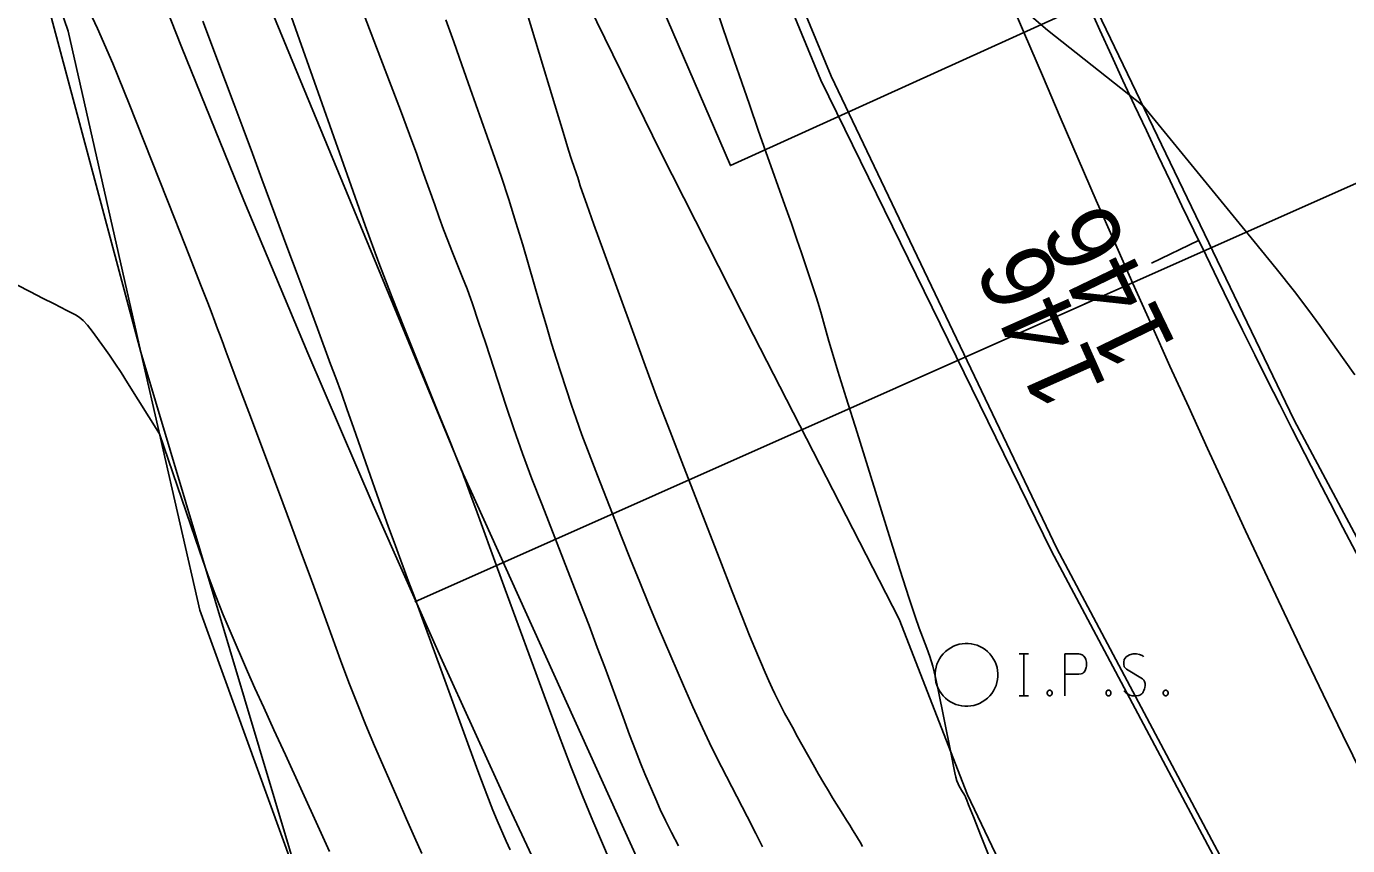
# Model space of a CAD drawing. Extents: x 2030588 to 2035216, y 462285 to 465007.
# Drawn here: x 2031264.3 to 2031314.8, y 464067.3 to 464098.6 of the extents above; entities that cross this region are included whole.
import ezdxf

# ---------------------------------------------------------------- set-up
doc = ezdxf.new("R2010")
doc.units = 0
for name, color, linetype in [('DT_X_Contour_Major', 7, 'Continuous'), ('DT_X_Contour_Minor', 7, 'Continuous'), ('DV_X_Property_Line', 7, 'Continuous'), ('GE_X_Alignment', 7, 'Continuous'), ('GE_X_Alignment_100_Stations', 7, 'Continuous'), ('MD_P_CONST_LIMITS', 7, 'Continuous'), ('PV_X_COP', 7, 'Continuous'), ('PV_X_EOP', 7, 'Continuous'), ('PV_X_Shoulder_Aggregate', 7, 'Continuous'), ('RW_X_CL', 7, 'Continuous'), ('RW_X_CL_100_Stations', 7, 'Continuous'), ('RW_X_Esmt_SH', 7, 'Continuous'), ('SV_P_Mon_Cells_Set', 7, 'Continuous'), ('SV_X_Break_Lines', 7, 'Continuous'), ('SV_X_Toe_of_Slope', 7, 'Continuous'), ('VG_X_Tree_Line_Lt', 7, 'Continuous')]:
    doc.layers.add(name, color=color, linetype=linetype)

msp = doc.modelspace()

# ---------------------------------------------------------------- linework, layer by layer
at = {"layer": 'DT_X_Contour_Major'}
for points in [[(2031282.783, 464101.292), (2031284.067, 464097.017), (2031284.494, 464095.597), (2031284.813, 464094.543), (2031285.024, 464093.856), (2031285.127, 464093.534), (2031285.256, 464093.166), (2031285.302, 464093.035), (2031285.341, 464092.917), (2031285.375, 464092.813), (2031285.402, 464092.722), (2031285.468, 464092.498), (2031285.542, 464092.277), (2031285.718, 464091.781), (2031285.995, 464091.012), (2031286.373, 464089.968), (2031287.514, 464086.819), (2031287.954, 464085.618), (2031288.417, 464084.377), (2031288.903, 464083.096), (2031289.412, 464081.775), (2031290.801, 464078.2), (2031291.275, 464076.983), (2031291.657, 464076.014), (2031291.946, 464075.292), (2031292.143, 464074.817), (2031292.544, 464073.883), (2031292.685, 464073.558), (2031292.806, 464073.284), (2031292.909, 464073.062), (2031292.993, 464072.891), (2031293.191, 464072.504), (2031293.283, 464072.328), (2031293.413, 464072.088), (2031293.579, 464071.786), (2031293.782, 464071.421), (2031294.372, 464070.363), (2031294.585, 464069.987), (2031294.779, 464069.649), (2031294.956, 464069.352), (2031295.114, 464069.094), (2031295.514, 464068.46), (2031295.654, 464068.235), (2031295.777, 464068.039), (2031295.882, 464067.87), (2031295.969, 464067.728), (2031296.176, 464067.387), (2031296.262, 464067.229)], [(2031279.413, 464066.965), (2031279.135, 464067.589), (2031278.833, 464068.273), (2031278.508, 464069.016), (2031277.612, 464071.078), (2031277.278, 464071.862), (2031276.951, 464072.669), (2031276.628, 464073.499), (2031276.311, 464074.35), (2031275.473, 464076.652), (2031275.143, 464077.553), (2031274.782, 464078.532), (2031274.391, 464079.586), (2031273.968, 464080.718), (2031272.798, 464083.837), (2031272.409, 464084.876), (2031272.117, 464085.655), (2031271.923, 464086.172), (2031271.827, 464086.429), (2031271.701, 464086.766), (2031271.653, 464086.895), (2031271.604, 464087.027), (2031271.553, 464087.163), (2031271.501, 464087.304), (2031271.36, 464087.684), (2031271.233, 464088.014), (2031270.956, 464088.72), (2031270.531, 464089.8), (2031269.956, 464091.255), (2031268.225, 464095.636), (2031267.599, 464097.178), (2031267.018, 464098.517), (2031266.484, 464099.653)]]:
    msp.add_lwpolyline(points, dxfattribs=at)
at = {"layer": 'DT_X_Contour_Minor'}
for points in [[(2031289.871, 464101.627), (2031291.105, 464098.019), (2031291.544, 464096.739), (2031291.935, 464095.608), (2031292.277, 464094.625), (2031292.571, 464093.789), (2031293.292, 464091.759), (2031293.543, 464091.048), (2031293.757, 464090.437), (2031293.932, 464089.927), (2031294.07, 464089.517), (2031294.386, 464088.558), (2031294.5, 464088.209), (2031294.602, 464087.881), (2031294.694, 464087.574), (2031294.775, 464087.289), (2031294.978, 464086.557), (2031295.101, 464086.132), (2031295.322, 464085.407), (2031295.638, 464084.381), (2031296.051, 464083.055), (2031297.28, 464079.117), (2031297.697, 464077.788), (2031298.027, 464076.756), (2031298.27, 464076.02), (2031298.426, 464075.581), (2031298.726, 464074.806), (2031298.836, 464074.488), (2031298.945, 464074.119), (2031299.05, 464073.696), (2031299.152, 464073.222), (2031299.624, 464070.883), (2031299.792, 464070.049), (2031299.829, 464069.882), (2031299.87, 464069.74), (2031299.914, 464069.624), (2031299.961, 464069.532), (2031300.09, 464069.319), (2031300.134, 464069.245), (2031300.169, 464069.182), (2031300.196, 464069.13), (2031300.213, 464069.089), (2031300.249, 464068.994), (2031300.318, 464068.816), (2031300.5, 464068.356), (2031300.795, 464067.612), (2031301.202, 464066.584)], [(2031276.986, 464099.628), (2031278.181, 464096.479), (2031278.596, 464095.383), (2031278.942, 464094.457), (2031279.221, 464093.699), (2031279.432, 464093.112), (2031279.906, 464091.77), (2031280.08, 464091.283), (2031280.248, 464090.826), (2031280.41, 464090.401), (2031280.566, 464090.006), (2031280.973, 464088.994), (2031281.143, 464088.551), (2031281.347, 464087.982), (2031281.586, 464087.286), (2031281.859, 464086.463), (2031282.632, 464084.101), (2031282.936, 464083.198), (2031283.267, 464082.262), (2031283.626, 464081.292), (2031284.012, 464080.288), (2031285.078, 464077.566), (2031285.461, 464076.583), (2031285.81, 464075.675), (2031286.124, 464074.843), (2031286.405, 464074.086), (2031287.107, 464072.169), (2031287.357, 464071.494), (2031287.58, 464070.908), (2031287.776, 464070.411), (2031287.945, 464070.003), (2031288.359, 464069.032), (2031288.53, 464068.648), (2031288.731, 464068.224), (2031288.962, 464067.761), (2031289.224, 464067.257)], [(2031271.042, 464098.792), (2031271.91, 464096.485), (2031272.241, 464095.603), (2031272.584, 464094.686), (2031272.939, 464093.735), (2031273.305, 464092.749), (2031274.296, 464090.074), (2031274.645, 464089.132), (2031274.949, 464088.313), (2031275.208, 464087.618), (2031275.421, 464087.044), (2031275.93, 464085.68), (2031276.128, 464085.145), (2031276.339, 464084.562), (2031276.564, 464083.933), (2031276.802, 464083.256), (2031277.455, 464081.387), (2031277.696, 464080.704), (2031277.926, 464080.055), (2031278.147, 464079.441), (2031278.359, 464078.862), (2031278.91, 464077.363), (2031279.142, 464076.731), (2031279.424, 464075.962), (2031279.756, 464075.054), (2031280.138, 464074.007), (2031281.225, 464071.032), (2031281.598, 464070.019), (2031281.901, 464069.212), (2031282.134, 464068.611), (2031282.298, 464068.216), (2031282.643, 464067.436), (2031282.795, 464067.096)], [(2031274.351, 464099.165), (2031274.735, 464098.083), (2031275.232, 464096.677), (2031276.708, 464092.494), (2031277.251, 464090.974), (2031277.775, 464089.551), (2031278.279, 464088.227), (2031278.763, 464086.999), (2031280.029, 464083.857), (2031280.444, 464082.825), (2031280.741, 464082.087), (2031280.92, 464081.643), (2031280.98, 464081.493), (2031280.983, 464081.484), (2031280.993, 464081.456), (2031281.023, 464081.376), (2031281.07, 464081.246), (2031281.137, 464081.066), (2031281.339, 464080.516), (2031281.475, 464080.146), (2031281.731, 464079.446), (2031282.108, 464078.418), (2031282.605, 464077.061), (2031284.092, 464073.004), (2031284.627, 464071.563), (2031285.116, 464070.284), (2031285.558, 464069.166), (2031285.955, 464068.209), (2031286.952, 464065.874)], [(2031280.333, 464098.841), (2031280.637, 464097.998), (2031280.948, 464097.125), (2031281.267, 464096.221), (2031282.129, 464093.772), (2031282.443, 464092.862), (2031282.738, 464091.969), (2031283.013, 464091.095), (2031283.27, 464090.237), (2031283.929, 464087.975), (2031284.164, 464087.175), (2031284.376, 464086.47), (2031284.564, 464085.862), (2031284.728, 464085.349), (2031285.133, 464084.11), (2031285.31, 464083.593), (2031285.534, 464082.973), (2031285.806, 464082.249), (2031286.127, 464081.421), (2031287.045, 464079.076), (2031287.392, 464078.201), (2031287.743, 464077.335), (2031288.097, 464076.48), (2031288.456, 464075.633), (2031289.419, 464073.388), (2031289.781, 464072.563), (2031290.143, 464071.768), (2031290.507, 464071.006), (2031290.872, 464070.275), (2031291.847, 464068.368), (2031292.178, 464067.722), (2031292.438, 464067.215)], [(2031315.086, 464085.27), (2031314.669, 464085.835), (2031313.746, 464087.158), (2031313.329, 464087.731), (2031312.772, 464088.458), (2031312.073, 464089.337), (2031311.234, 464090.37), (2031306.989, 464095.548), (2031303.336, 464098.443), (2031302.457, 464099.204)], [(2031275.886, 464067.033), (2031275.445, 464068.02), (2031274.198, 464070.727), (2031273.757, 464071.688), (2031273.37, 464072.539), (2031273.037, 464073.282), (2031272.757, 464073.915), (2031272.083, 464075.458), (2031271.821, 464076.084), (2031271.54, 464076.806), (2031271.24, 464077.622), (2031270.921, 464078.534), (2031269.388, 464083.011), (2031268.166, 464084.962), (2031267.915, 464085.358), (2031267.684, 464085.712), (2031267.474, 464086.021), (2031267.285, 464086.288), (2031266.807, 464086.941), (2031266.633, 464087.163), (2031266.47, 464087.342), (2031266.318, 464087.476), (2031266.176, 464087.565), (2031265.814, 464087.745), (2031265.625, 464087.839), (2031265.332, 464087.988), (2031264.935, 464088.19), (2031264.432, 464088.447), (2031262.954, 464089.202)]]:
    msp.add_lwpolyline(points, dxfattribs=at)
at = {"layer": 'DV_X_Property_Line'}
msp.add_line((2031279.145, 464076.588), (2031333.983, 464100.968), dxfattribs=at)
at = {"layer": 'GE_X_Alignment'}
msp.add_ellipse((2031674.732, 464267.126), major_axis=(-271.236, 302.23), ratio=0.999987, start_param=1.129391, end_param=1.463464, dxfattribs=at)
at = {"layer": 'GE_X_Alignment_100_Stations'}
msp.add_line((2031309.111, 464090.407), (2031307.311, 464089.537), dxfattribs=at)
at = {"layer": 'MD_P_CONST_LIMITS'}
msp.add_lwpolyline([(2031285.052, 464107.55), (2031291.211, 464093.27), (2031304.871, 464099.462)], dxfattribs=at)
at = {"layer": 'PV_X_COP'}
msp.add_lwpolyline([(2031345.188, 464029.832), (2031333.67, 464047.134), (2031321.647, 464066.894), (2031312.766, 464083.536), (2031304.429, 464100.871), (2031297.296, 464118.161), (2031290.962, 464134.785), (2031285.598, 464151.007), (2031280.258, 464168.89), (2031275.568, 464187.058), (2031270.599, 464208.238), (2031269.533, 464213.253), (2031265.078, 464235.308), (2031261.071, 464256.548), (2031257.559, 464275.914), (2031253.749, 464297.335), (2031250.237, 464316.556), (2031248.155, 464328.465)], dxfattribs=at)
at = {"layer": 'PV_X_EOP'}
msp.add_lwpolyline([(2031336.828, 464023.844), (2031324.967, 464041.493), (2031320.199, 464048.99), (2031315.567, 464056.548), (2031312.619, 464061.808), (2031303.69, 464078.622), (2031295.06, 464096.69), (2031287.81, 464114.209)], dxfattribs=at)
at = {"layer": 'PV_X_Shoulder_Aggregate'}
msp.add_lwpolyline([(2031320.199, 464048.99), (2031315.35, 464056.493), (2031312.439, 464061.67), (2031303.482, 464078.527), (2031294.666, 464096.538), (2031287.417, 464114.11)], dxfattribs=at)
at = {"layer": 'RW_X_CL'}
msp.add_ellipse((2031830.081, 464321.523), major_axis=(-382.715, 426.319), ratio=0.999987, start_param=0.998751, end_param=1.776295, dxfattribs=at)
at = {"layer": 'RW_X_CL_100_Stations'}
msp.add_line((2031306.587, 464088.788), (2031304.76, 464087.976), dxfattribs=at)
at = {"layer": 'RW_X_Esmt_SH'}
msp.add_lwpolyline([(2031318.888, 464001.895), (2031315.557, 464007.284), (2031312.284, 464012.707), (2031309.068, 464018.165), (2031305.909, 464023.656), (2031302.808, 464029.18), (2031299.765, 464034.736), (2031296.781, 464040.324), (2031293.856, 464045.943), (2031290.99, 464051.593), (2031288.184, 464057.272), (2031285.437, 464062.981), (2031282.75, 464068.717), (2031280.124, 464074.482), (2031277.559, 464080.275), (2031275.054, 464086.093), (2031272.611, 464091.938), (2031270.23, 464097.808), (2031267.91, 464103.703)], dxfattribs=at)
at = {"layer": 'SV_P_Mon_Cells_Set'}
for p, q in [((2031302.255, 464074.593), (2031302.608, 464074.593)), ((2031302.431, 464072.993), (2031302.431, 464074.593)), ((2031302.255, 464072.993), (2031302.608, 464072.993))]:
    msp.add_line(p, q, dxfattribs=at)
for points in [[(2031303.997, 464072.993), (2031303.997, 464074.593), (2031304.526, 464074.593), (2031304.581, 464074.58), (2031304.658, 464074.555), (2031304.691, 464074.529), (2031304.724, 464074.504), (2031304.768, 464074.441), (2031304.801, 464074.378), (2031304.823, 464074.278), (2031304.823, 464074.126), (2031304.812, 464074.076), (2031304.79, 464074), (2031304.746, 464073.912), (2031304.702, 464073.874), (2031304.669, 464073.849), (2031304.614, 464073.824), (2031304.526, 464073.812), (2031303.997, 464073.812)], [(2031307.006, 464074.479), (2031306.984, 464074.504), (2031306.95, 464074.529), (2031306.851, 464074.567), (2031306.73, 464074.593), (2031306.642, 464074.593), (2031306.609, 464074.593), (2031306.465, 464074.555), (2031306.344, 464074.479), (2031306.267, 464074.378), (2031306.245, 464074.278), (2031306.245, 464074.202), (2031306.267, 464074.101), (2031306.355, 464074.013), (2031306.962, 464073.635), (2031307.017, 464073.585), (2031307.039, 464073.534), (2031307.061, 464073.459), (2031307.061, 464073.383), (2031307.05, 464073.308), (2031307.039, 464073.257), (2031307.017, 464073.194), (2031306.994, 464073.144), (2031306.972, 464073.106), (2031306.939, 464073.068), (2031306.906, 464073.043), (2031306.862, 464073.018), (2031306.829, 464073.005), (2031306.73, 464072.993), (2031306.576, 464072.993), (2031306.477, 464073.018), (2031306.333, 464073.106), (2031306.245, 464073.182)], [(2031303.39, 464073.207), (2031303.445, 464073.207), (2031303.479, 464073.182), (2031303.512, 464073.131), (2031303.512, 464073.068), (2031303.479, 464073.018), (2031303.445, 464072.993), (2031303.39, 464072.993), (2031303.357, 464073.018), (2031303.324, 464073.068), (2031303.324, 464073.131), (2031303.357, 464073.182), (2031303.39, 464073.207)], [(2031305.639, 464073.207), (2031305.694, 464073.207), (2031305.727, 464073.182), (2031305.76, 464073.131), (2031305.76, 464073.068), (2031305.727, 464073.018), (2031305.694, 464072.993), (2031305.639, 464072.993), (2031305.606, 464073.018), (2031305.573, 464073.068), (2031305.573, 464073.131), (2031305.606, 464073.182), (2031305.639, 464073.207)], [(2031307.821, 464073.207), (2031307.876, 464073.207), (2031307.909, 464073.182), (2031307.942, 464073.131), (2031307.942, 464073.068), (2031307.909, 464073.018), (2031307.876, 464072.993), (2031307.821, 464072.993), (2031307.788, 464073.018), (2031307.755, 464073.068), (2031307.755, 464073.131), (2031307.788, 464073.182), (2031307.821, 464073.207)]]:
    msp.add_lwpolyline(points, dxfattribs=at)
msp.add_ellipse((2031300.236, 464073.791), major_axis=(-0.801, 0.894), ratio=0.999987, dxfattribs=at)
at = {"layer": 'SV_X_Break_Lines'}
msp.add_lwpolyline([(2031332.936, 464021.342), (2031326.956, 464028.327), (2031320.255, 464037.227), (2031317.729, 464040.895), (2031314.591, 464045.376), (2031310.796, 464052.164), (2031308.581, 464056.233), (2031305.895, 464059.016), (2031304.004, 464061.369), (2031300.275, 464069.207), (2031297.665, 464075.924), (2031292.09, 464086.785), (2031288.534, 464093.79), (2031283.056, 464105)], dxfattribs=at)
at = {"layer": 'SV_X_Toe_of_Slope'}
msp.add_lwpolyline([(2031299.164, 463999.49), (2031295.631, 464009.319), (2031291.355, 464020.586), (2031287.38, 464029.092), (2031284.977, 464037.012), (2031281.132, 464045.775), (2031277.306, 464058.546), (2031274.914, 464065.259), (2031270.925, 464076.266), (2031268.677, 464086.131), (2031265.895, 464098.404), (2031263.605, 464105.114), (2031260.305, 464113.058), (2031258.152, 464123.882), (2031257.156, 464130.278)], dxfattribs=at)
at = {"layer": 'VG_X_Tree_Line_Lt'}
msp.add_lwpolyline([(2031299.164, 463999.49), (2031291.355, 464020.586), (2031284.977, 464037.012), (2031277.306, 464058.546), (2031274.914, 464065.259), (2031268.677, 464086.131), (2031263.605, 464105.114), (2031258.152, 464123.882), (2031257.156, 464130.278), (2031256.558, 464137.576), (2031262.635, 464138.353), (2031267.388, 464116.03), (2031272.778, 464101.364), (2031280.991, 464081.48), (2031292.736, 464055.542), (2031301.293, 464044.324), (2031311.848, 464027.211), (2031308.441, 464005.36)], dxfattribs=at)

# ---------------------------------------------------------------- texts
at = {"layer": 'GE_X_Alignment_100_Stations'}
msp.add_text('146', height=2.7997, rotation=115.7968, dxfattribs=at).set_placement((2031308.277, 464086.389))
at = {"layer": 'RW_X_CL_100_Stations'}
msp.add_text('146', height=2.7997, rotation=113.9694, dxfattribs=at).set_placement((2031305.625, 464084.799))

doc.saveas('drawing.dxf')
